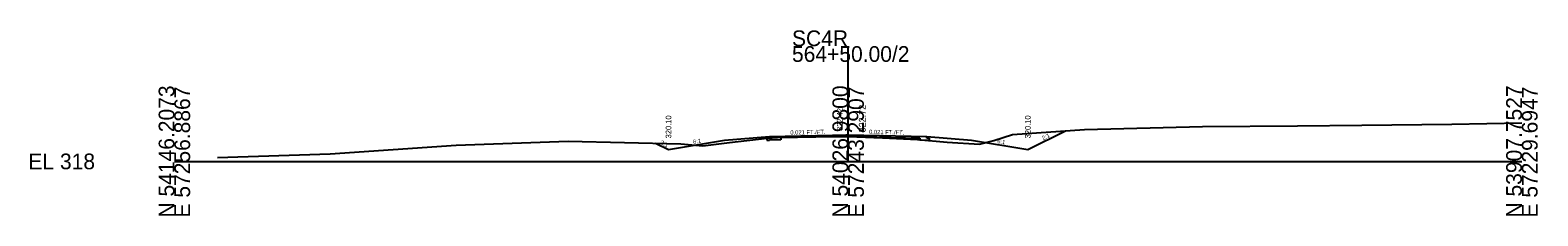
# Model space of a CAD drawing. Extents: x 9740 to 17409, y 8856 to 28416.
# Drawn here: x 12740.2 to 13008.7, y 25361.7 to 25394.7 of the extents above; entities that cross this region are included whole.
import ezdxf

# ---------------------------------------------------------------- set-up
doc = ezdxf.new("R2010")
doc.units = 0
for name, color, linetype in [('Level 10', 7, 'Continuous'), ('Level 11', 7, 'Continuous'), ('Level 12', 7, 'Continuous'), ('Level 32', 7, 'Continuous'), ('Level 33', 7, 'Continuous'), ('Level 53', 7, 'Continuous'), ('Level 59', 7, 'Continuous'), ('Level 6', 7, 'Continuous'), ('Level 60', 7, 'Continuous'), ('Level 63', 7, 'Continuous'), ('Level 7', 7, 'Continuous')]:
    doc.layers.add(name, color=color, linetype=linetype)

msp = doc.modelspace()

# ---------------------------------------------------------------- linework, layer by layer
at = {"layer": 'Level 11'}
for p, q in [((12871.85, 25375.51), (12871.35, 25375.5)), ((12871.35, 25375.5), (12871.35, 25375.16)), ((12871.35, 25375.16), (12871.85, 25375.17)), ((12871.85, 25375.81), (12871.85, 25375.51)), ((12899.85, 25375.51), (12899.85, 25375.81)), ((12900.35, 25375.5), (12899.85, 25375.51)), ((12899.85, 25375.17), (12900.35, 25375.16)), ((12900.35, 25375.16), (12900.35, 25375.5))]:
    msp.add_line(p, q, dxfattribs=at)
at = {"layer": 'Level 12'}
for p, q in [((12873.89, 25375.21), (12871.85, 25375.17)), ((12873.89, 25375.69), (12873.89, 25375.21)), ((12898.64, 25375.26), (12898.64, 25375.19)), ((12898.64, 25375.19), (12899.85, 25375.17))]:
    msp.add_line(p, q, dxfattribs=at)
at = {"layer": 'Level 53'}
for p, q in [((12885.85, 25375.8), (12873.89, 25375.55)), ((12885.85, 25375.8), (12898.64, 25375.53)), ((12898.64, 25375.53), (12898.64, 25375.26))]:
    msp.add_line(p, q, dxfattribs=at)
at = {"layer": 'Level 59'}
for p, q in [((12871.85, 25375.81), (12885.85, 25376.1)), ((12885.85, 25376.1), (12899.85, 25375.81))]:
    msp.add_line(p, q, dxfattribs=at)
at = {"layer": 'Level 6'}
for p, q in [((12863.85, 25375.14), (12871.85, 25375.81)), ((12899.85, 25375.81), (12907.85, 25375.14))]:
    msp.add_line(p, q, dxfattribs=at)
at = {"layer": 'Level 60'}
for p, q in [((12915.12, 25376.15), (12927.94, 25377.08)), ((12927.94, 25377.08), (12948.97, 25377.58)), ((12948.97, 25377.58), (12965.86, 25377.7)), ((12965.86, 25377.7), (12977.37, 25377.83)), ((12977.37, 25377.83), (12993.38, 25377.99)), ((12993.38, 25377.99), (13005.85, 25378.22)), ((12793.59, 25372.71), (12816.01, 25374.26)), ((12816.01, 25374.26), (12835.96, 25375.01)), ((12835.96, 25375.01), (12856.03, 25374.51)), ((12856.03, 25374.51), (12859.98, 25374.12)), ((12859.98, 25374.12), (12864.73, 25374.72)), ((12864.73, 25374.72), (12871.41, 25375.49)), ((12871.41, 25375.49), (12874.17, 25375.71)), ((12874.17, 25375.71), (12880.1, 25375.73)), ((12880.1, 25375.73), (12885.85, 25375.8)), ((12885.85, 25375.8), (12891.97, 25375.6)), ((12891.97, 25375.6), (12898.21, 25375.29)), ((12898.21, 25375.29), (12903.51, 25374.83)), ((12903.51, 25374.83), (12909.24, 25374.45)), ((12909.24, 25374.45), (12911.82, 25375.08)), ((12911.82, 25375.08), (12915.12, 25376.15)), ((12773.5, 25372.06), (12793.59, 25372.71))]:
    msp.add_line(p, q, dxfattribs=at)
at = {"layer": 'Level 63'}
for p, q in [((12885.85, 25371.38), (12885.85, 25391.9)), ((12765.85, 25371.38), (12885.85, 25371.38)), ((12885.85, 25371.38), (13005.85, 25371.38))]:
    msp.add_line(p, q, dxfattribs=at)
at = {"layer": 'Level 7'}
for p, q in [((12917.85, 25373.48), (12924.57, 25376.83)), ((12851.56, 25374.62), (12853.85, 25373.48)), ((12853.85, 25373.48), (12863.85, 25375.14)), ((12907.85, 25375.14), (12917.85, 25373.48))]:
    msp.add_line(p, q, dxfattribs=at)

# ---------------------------------------------------------------- texts
at = {"layer": 'Level 10'}
msp.add_text('322.42', height=1, rotation=90, dxfattribs=at).set_placement((12884.85, 25376.8))
at = {"layer": 'Level 32'}
for s, rotation, p in [('0.021 FT./FT.', 1.1916, (12875.56, 25376.14)), ('0.021 FT./FT.', 358.8084, (12889.57, 25376.27)), ('2:1', 333.435, (12852.31, 25374.52)), ('6:1', 9.4623, (12858.29, 25374.47)), ('6:1', 350.5377, (12912.37, 25374.64)), ('2:1', 26.5651, (12920.59, 25375.12))]:
    msp.add_text(s, height=0.75, rotation=rotation, dxfattribs=at).set_placement(p)
at = {"layer": 'Level 33'}
for p in [(12854.35, 25375.48), (12918.35, 25375.48)]:
    msp.add_text('320.10', height=1, rotation=90, dxfattribs=at).set_placement(p)
at = {"layer": 'Level 59'}
msp.add_text(' 322.72', height=1.2, rotation=90, dxfattribs=at).set_placement((12888.96, 25376.1))
at = {"layer": 'Level 63'}
for s, p in [('SC4R', (12875.85, 25391.9)), ('564+50.00/2', (12875.85, 25389.1)), ('EL 318', (12739.85, 25369.98))]:
    msp.add_text(s, height=2.8, dxfattribs=at).set_placement(p)
for s, p in [('N 54146.2073', (12765.85, 25361.38)), ('E 57256.8867', (12768.65, 25361.38)), ('N 54026.9800', (12885.85, 25361.38)), ('E 57243.2907', (12888.65, 25361.38)), ('N 53907.7527', (13005.85, 25361.38)), ('E 57229.6947', (13008.65, 25361.38))]:
    msp.add_text(s, height=2.8, rotation=90, dxfattribs=at).set_placement(p)

doc.saveas('drawing.dxf')
